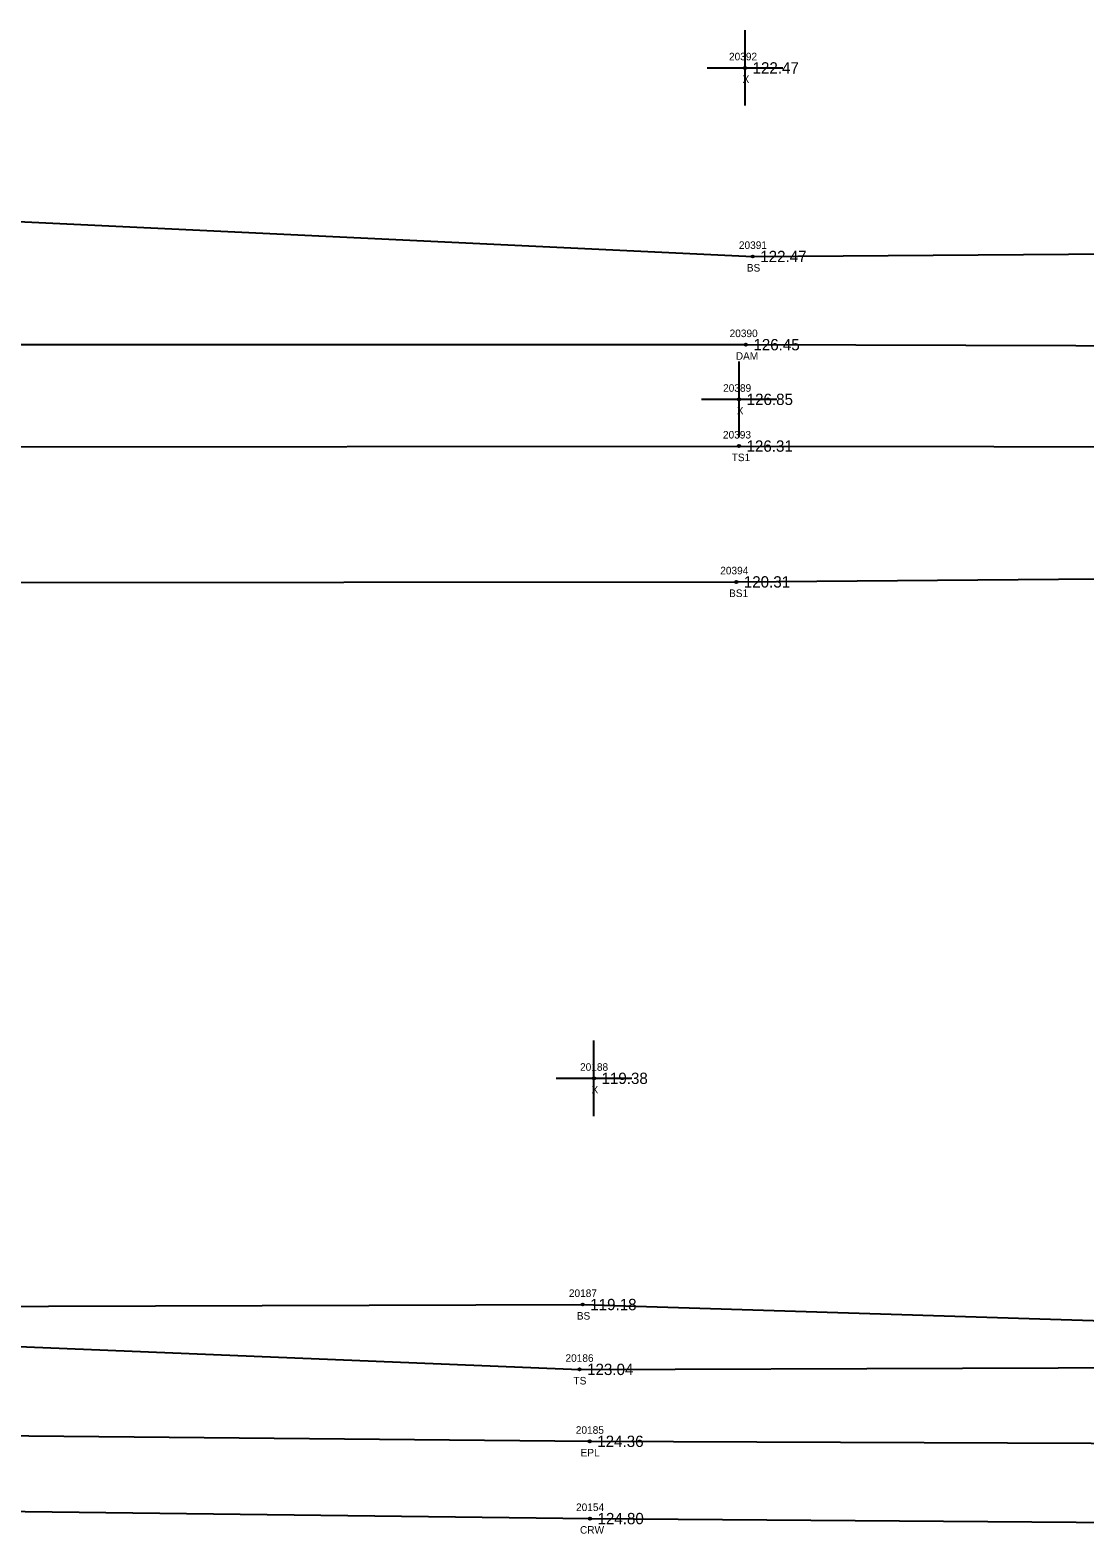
# Model space of a CAD drawing. Extents: x 2375812 to 2377225, y 1024470 to 1025135.
# Drawn here: x 2376791.6 to 2376931.3, y 1024920.1 to 1025119.8 of the extents above; entities that cross this region are included whole.
import ezdxf

# ---------------------------------------------------------------- set-up
doc = ezdxf.new("R2010")
doc.units = 0
for name, color, linetype in [('RD_DTM_BkLn1', 7, 'Continuous'), ('RD_DTM_BkLn2', 7, 'Continuous'), ('RD_DTM_BkLn_txCode', 7, 'Continuous'), ('RD_EX_Dam', 7, 'Continuous'), ('RD_EX_Dam_txCode', 7, 'Continuous'), ('RD_EX_Misc', 7, 'Continuous'), ('RD_EX_Misc_txCode', 7, 'Continuous'), ('RD_EX_Road', 7, 'Continuous'), ('RD_EX_Road_txCode', 7, 'Continuous'), ('RD_EX_TX_Dam_ELEV', 7, 'Continuous'), ('RD_EX_TX_Misc_ELEV', 7, 'Continuous'), ('RD_EX_TX_Road_ELEV', 7, 'Continuous'), ('RD_HC_Survey_ELEV', 7, 'Continuous'), ('RD_HC_Survey_txCode', 7, 'Continuous'), ('RD_SMD_Locator', 7, 'Continuous')]:
    doc.layers.add(name, color=color, linetype=linetype)

msp = doc.modelspace()

# ---------------------------------------------------------------- linework, layer by layer
at = {"layer": 'RD_DTM_BkLn1'}
msp.add_lwpolyline([(2376561.75, 1024926.35), (2376659.86, 1024925.07), (2376762.41, 1024923.95), (2376865.76, 1024922.65), (2376965.3, 1024921.9), (2377063.64, 1024920.86), (2377113.34, 1024920.1), (2377166.94, 1024920.12), (2377217.3, 1024921.22)], dxfattribs=at)
at = {"layer": 'RD_DTM_BkLn2'}
for points in [[(2376552.99, 1025053.79), (2376560.85, 1025063.21), (2376567.06, 1025075.76), (2376572.77, 1025085.75), (2376582.8, 1025094.03), (2376679.85, 1025092.48), (2376779.73, 1025094.91), (2376887.32, 1025089.81), (2376988.9, 1025090.57), (2377106.48, 1025091.22), (2377202.62, 1025093.89)], [(2376580.3, 1025079.96), (2376576.42, 1025074.43), (2376572.95, 1025066.08), (2376567.78, 1025062.13), (2376680.13, 1025064), (2376781.64, 1025064.6), (2376885.5, 1025064.7), (2376986.85, 1025064.56), (2377105.91, 1025065.21), (2377201.99, 1025063.63)], [(2376554.71, 1025040.88), (2376679.34, 1025046.02), (2376781.14, 1025046.61), (2376885.14, 1025046.71), (2376986.57, 1025047.57), (2377105.91, 1025056.21), (2377201.82, 1025050.7)], [(2376538.09, 1024944), (2376550.49, 1024951.37), (2376563.43, 1024953.34), (2376659.84, 1024952.77), (2376765.68, 1024950.71), (2376864.8, 1024951), (2376966.18, 1024947.81), (2377065.88, 1024945.38), (2377115.79, 1024945.18), (2377168.04, 1024944.37), (2377216.91, 1024944.34)], [(2376561.81, 1024938.95), (2376565.65, 1024944.33), (2376658.56, 1024947.18), (2376764.14, 1024946.5), (2376864.38, 1024942.41), (2376965.82, 1024942.74), (2377065.85, 1024939.54), (2377114.14, 1024940.04), (2377167.94, 1024941.05), (2377217.02, 1024940.65)]]:
    msp.add_lwpolyline(points, dxfattribs=at)
at = {"layer": 'RD_EX_Dam'}
msp.add_lwpolyline([(2376580.3, 1025079.96), (2376679.85, 1025076.24), (2376781.56, 1025078.14), (2376886.41, 1025078.13), (2376988.46, 1025077.85), (2377107.1, 1025079.69), (2377202.68, 1025079.96)], dxfattribs=at)
at = {"layer": 'RD_EX_Misc'}
for p, q in [((2376886.3, 1025109.79), (2376886.3, 1025119.79)), ((2376881.3, 1025114.79), (2376891.3, 1025114.79)), ((2376885.52, 1025065.89), (2376885.52, 1025075.89)), ((2376880.52, 1025070.89), (2376890.52, 1025070.89)), ((2376866.29, 1024975.96), (2376866.29, 1024985.96)), ((2376861.29, 1024980.96), (2376871.29, 1024980.96))]:
    msp.add_line(p, q, dxfattribs=at)
at = {"layer": 'RD_EX_Road'}
msp.add_lwpolyline([(2376561.85, 1024938.22), (2376659.62, 1024935.3), (2376763.51, 1024933.89), (2376865.73, 1024932.88), (2376965.35, 1024932.49), (2377065.13, 1024930.78), (2377114.03, 1024930.18), (2377167.22, 1024930.19), (2377217.07, 1024931.12)], dxfattribs=at)
at = {"layer": 'RD_SMD_Locator'}
for centre in [(2376886.3, 1025114.79), (2376887.32, 1025089.81), (2376886.41, 1025078.13), (2376885.52, 1025070.89), (2376885.5, 1025064.7), (2376885.14, 1025046.71), (2376866.29, 1024980.96), (2376864.8, 1024951), (2376864.38, 1024942.41), (2376865.73, 1024932.88), (2376865.76, 1024922.65)]:
    msp.add_circle(centre, 0.15, dxfattribs=at)

# ---------------------------------------------------------------- texts
at = {"layer": 'RD_DTM_BkLn_txCode'}
for s, p in [('20391', (2376885.49, 1025090.81)), ('BS', (2376886.54, 1025087.81)), ('20393', (2376883.38, 1025065.7)), ('TS1', (2376884.54, 1025062.7)), ('20394', (2376883.02, 1025047.71)), ('BS1', (2376884.19, 1025044.71)), ('20187', (2376862.97, 1024952)), ('BS', (2376864.02, 1024949)), ('20186', (2376862.52, 1024943.41)), ('TS', (2376863.58, 1024940.41))]:
    msp.add_text(s, height=1, dxfattribs=at).set_placement(p)
at = {"layer": 'RD_EX_Dam_txCode'}
for s, p in [('20390', (2376884.26, 1025079.13)), ('DAM', (2376885.08, 1025076.13))]:
    msp.add_text(s, height=1, dxfattribs=at).set_placement(p)
at = {"layer": 'RD_EX_Misc_txCode'}
for s, p in [('20392', (2376884.18, 1025115.79)), ('X', (2376885.98, 1025112.79)), ('20389', (2376883.4, 1025071.89)), ('X', (2376885.21, 1025068.89)), ('20188', (2376864.45, 1024981.96)), ('X', (2376865.97, 1024978.96))]:
    msp.add_text(s, height=1, dxfattribs=at).set_placement(p)
at = {"layer": 'RD_EX_Road_txCode'}
for s, p in [('20185', (2376863.89, 1024933.88)), ('EPL', (2376864.52, 1024930.88))]:
    msp.add_text(s, height=1, dxfattribs=at).set_placement(p)
at = {"layer": 'RD_EX_TX_Dam_ELEV'}
msp.add_text('126.45', height=1.5, dxfattribs=at).set_placement((2376887.41, 1025077.38))
at = {"layer": 'RD_EX_TX_Misc_ELEV'}
for s, p in [('122.47', (2376887.3, 1025114.04)), ('122.47', (2376888.32, 1025089.06)), ('126.85', (2376886.52, 1025070.14)), ('126.31', (2376886.5, 1025063.95)), ('120.31', (2376886.14, 1025045.96)), ('119.38', (2376867.29, 1024980.21)), ('119.18', (2376865.8, 1024950.25)), ('123.04', (2376865.38, 1024941.66))]:
    msp.add_text(s, height=1.5, dxfattribs=at).set_placement(p)
at = {"layer": 'RD_EX_TX_Road_ELEV'}
msp.add_text('124.36', height=1.5, dxfattribs=at).set_placement((2376866.73, 1024932.13))
at = {"layer": 'RD_HC_Survey_ELEV'}
msp.add_text('124.80', height=1.5, dxfattribs=at).set_placement((2376866.76, 1024921.9))
at = {"layer": 'RD_HC_Survey_txCode'}
for s, p in [('20154', (2376863.92, 1024923.65)), ('CRW', (2376864.44, 1024920.65))]:
    msp.add_text(s, height=1, dxfattribs=at).set_placement(p)

doc.saveas('drawing.dxf')
